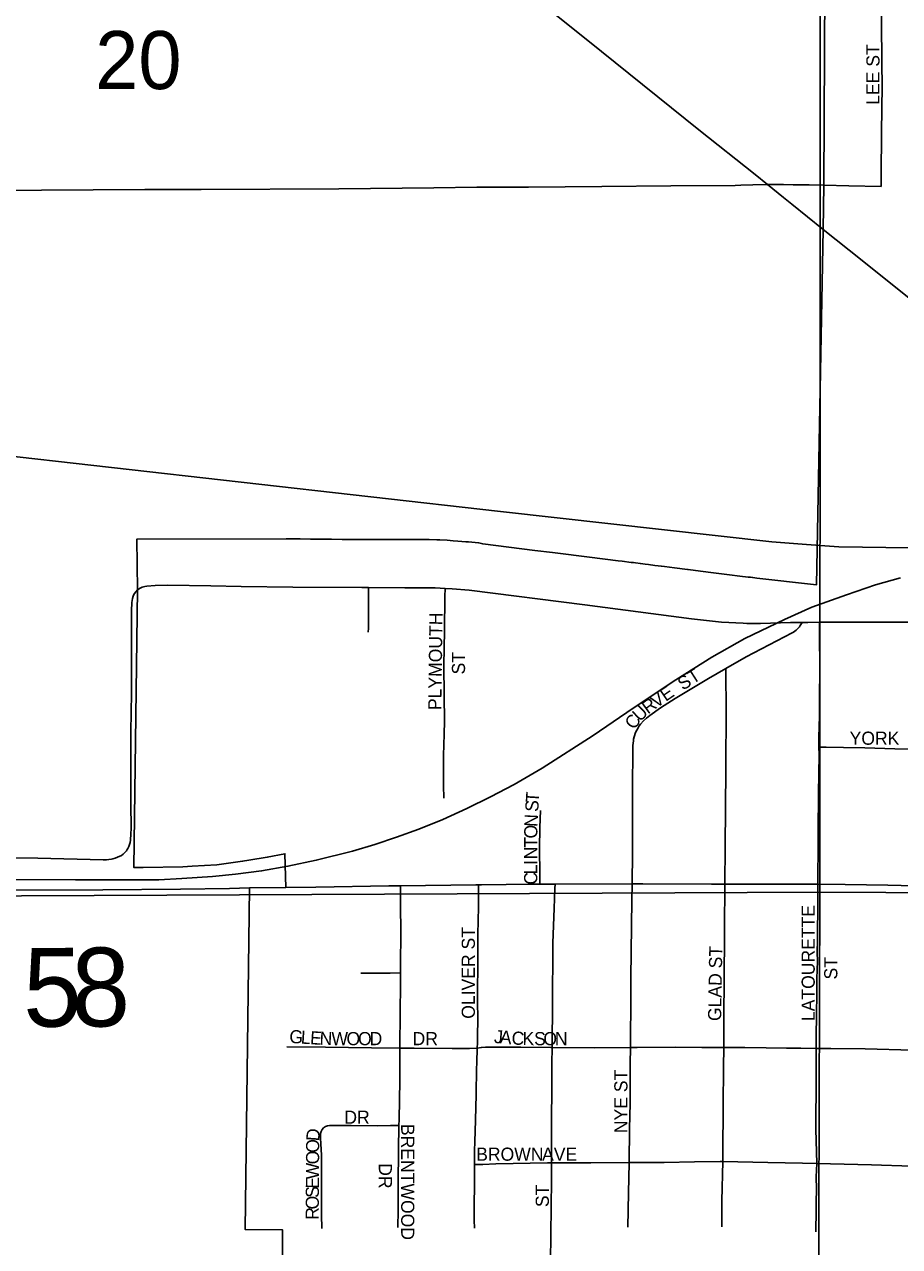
# Model space of a CAD drawing. Extents: x -97 to 34, y -21 to 22.
# Drawn here: x 4.025 to 4.656, y 19.223 to 20.104 of the extents above; entities that cross this region are included whole.
import ezdxf

# ---------------------------------------------------------------- set-up
doc = ezdxf.new("R2010")
doc.units = 0
for name, color, linetype in [('GM_X_City_Street', 7, 'Continuous'), ('GM_X_City_Street_Text', 7, 'Continuous'), ('GM_X_Corporation', 7, 'Continuous'), ('GM_X_County_Road', 7, 'Continuous'), ('GM_X_County_Road_Text', 7, 'Continuous'), ('GM_X_Rail_Line', 7, 'Continuous'), ('GM_X_Section', 7, 'Continuous'), ('GM_X_Section_Text', 7, 'Continuous'), ('GM_X_State_Route', 7, 'Continuous')]:
    doc.layers.add(name, color=color, linetype=linetype)

msp = doc.modelspace()

# ---------------------------------------------------------------- linework, layer by layer
at = {"layer": 'GM_X_City_Street'}
for points in [[(4.64294, 19.98749), (4.64296, 19.99531), (4.64307, 20.02635), (4.64353, 20.06045), (4.64344, 20.07596), (4.64318, 20.1069), (4.64326, 20.11613), (4.64352, 20.13152), (4.64362, 20.16222), (4.64369, 20.17921)], [(4.60166, 19.98837), (4.6197, 19.98805), (4.64294, 19.98749)], [(4.27324, 19.66609), (4.27329, 19.66906), (4.2734, 19.6928), (4.27343, 19.69838)], [(4.32766, 19.54637), (4.3274, 19.55557), (4.32738, 19.57718), (4.32783, 19.59263), (4.32815, 19.60191), (4.32799, 19.62049), (4.3277, 19.64218), (4.32808, 19.66696), (4.32847, 19.69175), (4.32856, 19.69766)], [(4.53101, 19.63991), (4.54552, 19.64826), (4.57865, 19.66563), (4.57969, 19.66618), (4.58067, 19.66686), (4.58171, 19.66757), (4.58319, 19.66891), (4.584, 19.66986), (4.58463, 19.67086), (4.58596, 19.67309)], [(4.59809, 19.58323), (4.59805, 19.59022), (4.59838, 19.60574), (4.59836, 19.61506), (4.59859, 19.643), (4.59858, 19.66162), (4.59856, 19.67326)], [(4.46586, 19.59361), (4.46676, 19.5955), (4.46768, 19.5972), (4.46847, 19.59843), (4.46949, 19.59974), (4.47159, 19.60203), (4.47382, 19.60406), (4.47625, 19.60599), (4.48396, 19.61147), (4.49445, 19.61823), (4.51851, 19.6327), (4.53101, 19.63991)], [(4.53016, 19.4844), (4.53038, 19.51129), (4.53106, 19.56739), (4.53111, 19.61103), (4.53103, 19.63594), (4.53101, 19.63991)], [(4.46333, 19.4846), (4.4636, 19.50688), (4.46361, 19.55348), (4.46384, 19.58144), (4.46396, 19.58438), (4.4643, 19.58762), (4.46448, 19.589), (4.46484, 19.59067), (4.46586, 19.59361)], [(4.59728, 19.48431), (4.59751, 19.51571), (4.59754, 19.53124), (4.59782, 19.54055), (4.59779, 19.54986), (4.59812, 19.57781), (4.59809, 19.58323)], [(4.59809, 19.58323), (4.60332, 19.58314), (4.61567, 19.58295), (4.63108, 19.58269), (4.65267, 19.58195), (4.6676, 19.58171)], [(4.39685, 19.48426), (4.39682, 19.49168), (4.39677, 19.50997), (4.3968, 19.52523), (4.39734, 19.53744)], [(4.21384, 19.482), (4.23545, 19.48214), (4.28815, 19.48317), (4.29643, 19.48326)], [(4.2965, 19.4205), (4.2965, 19.43005), (4.29673, 19.44542), (4.29641, 19.47352), (4.29643, 19.47975), (4.29643, 19.48326)], [(4.29643, 19.48326), (4.35083, 19.48382), (4.3526, 19.48383)], [(4.35178, 19.3661), (4.35187, 19.36999), (4.35205, 19.37587), (4.35222, 19.38567), (4.35197, 19.40126), (4.35201, 19.40437), (4.35197, 19.41358), (4.35215, 19.41935), (4.35224, 19.42584), (4.3521, 19.43205), (4.35214, 19.4373), (4.3522, 19.44484), (4.35223, 19.44952), (4.35242, 19.45668), (4.35261, 19.46919), (4.35262, 19.47572), (4.35263, 19.47882), (4.35263, 19.48259), (4.3526, 19.48383)], [(4.3526, 19.48383), (4.35484, 19.48386), (4.39049, 19.48423), (4.39685, 19.48426)], [(4.39685, 19.48426), (4.40783, 19.48432)], [(4.40572, 19.3666), (4.40576, 19.37053), (4.40608, 19.39538), (4.40631, 19.44203), (4.40712, 19.46692), (4.40771, 19.48132), (4.40783, 19.48432)], [(4.40783, 19.48432), (4.46333, 19.4846)], [(4.46214, 19.36657), (4.46227, 19.37645), (4.46241, 19.39506), (4.4625, 19.41679), (4.4632, 19.4727), (4.46333, 19.4846)], [(4.46333, 19.4846), (4.47113, 19.48464), (4.52072, 19.4844), (4.53016, 19.4844)], [(4.52943, 19.36656), (4.52955, 19.39289), (4.52975, 19.41156), (4.5299, 19.45207), (4.53016, 19.4844)], [(4.53016, 19.4844), (4.58586, 19.48437), (4.59728, 19.48431)], [(4.59598, 19.36586), (4.59597, 19.36985), (4.59633, 19.39467), (4.59643, 19.40087), (4.59647, 19.40397), (4.59661, 19.41327), (4.59658, 19.41637), (4.59694, 19.42878), (4.59679, 19.43499), (4.59697, 19.44431), (4.59719, 19.47225), (4.59728, 19.48431)], [(4.59728, 19.48431), (4.61686, 19.4842), (4.63233, 19.48391), (4.64781, 19.48371), (4.66685, 19.48317)], [(4.26799, 19.42017), (4.28342, 19.42017), (4.28639, 19.42019), (4.28912, 19.42027), (4.2965, 19.4205)], [(4.296, 19.36614), (4.29621, 19.39256), (4.29651, 19.41125), (4.2965, 19.4205)], [(4.21446, 19.36699), (4.2425, 19.36673), (4.27556, 19.36628), (4.296, 19.36614)], [(4.29538, 19.31033), (4.29545, 19.31465), (4.29599, 19.3427), (4.29599, 19.36452), (4.296, 19.36614)], [(4.296, 19.36614), (4.3062, 19.36608), (4.3337, 19.36589), (4.34616, 19.36584), (4.35178, 19.3661)], [(4.34981, 19.28207), (4.34981, 19.28297), (4.3498, 19.29233), (4.35005, 19.29855), (4.35041, 19.31414), (4.35102, 19.33276), (4.35098, 19.339), (4.35115, 19.34521), (4.35124, 19.35099), (4.35142, 19.35569), (4.35178, 19.3661)], [(4.35178, 19.3661), (4.35476, 19.36664), (4.35771, 19.3669), (4.36148, 19.3669), (4.38314, 19.36683), (4.4049, 19.36661), (4.40572, 19.3666)], [(4.40531, 19.28331), (4.4054, 19.31772), (4.40553, 19.33327), (4.4056, 19.35502), (4.40572, 19.3666)], [(4.40572, 19.3666), (4.43596, 19.36629), (4.46214, 19.36657)], [(4.46118, 19.28359), (4.46154, 19.30792), (4.46191, 19.32648), (4.462, 19.35475), (4.46214, 19.36657)], [(4.46214, 19.36657), (4.46703, 19.36662), (4.49499, 19.3667), (4.51361, 19.36654), (4.52943, 19.36656)], [(4.52872, 19.28426), (4.5289, 19.29013), (4.529, 19.32439), (4.52937, 19.35241), (4.52943, 19.36656)], [(4.52943, 19.36656), (4.54459, 19.36658), (4.55999, 19.36628), (4.57465, 19.36601), (4.5849, 19.36599), (4.59598, 19.36586)], [(4.59643, 19.28289), (4.59644, 19.28294), (4.59579, 19.30777), (4.59603, 19.34502), (4.59598, 19.36586)], [(4.59598, 19.36586), (4.60664, 19.36575), (4.63147, 19.36554), (4.66562, 19.36466), (4.6658, 19.36465)], [(4.23966, 19.23605), (4.2396, 19.24585), (4.23955, 19.25491), (4.23944, 19.26759), (4.23944, 19.27847), (4.23944, 19.28892), (4.23887, 19.30119), (4.23883, 19.3046), (4.23922, 19.306), (4.23999, 19.30746), (4.24103, 19.30857), (4.24231, 19.3095), (4.24375, 19.30997), (4.24531, 19.31024), (4.25467, 19.31038), (4.2609, 19.31031), (4.27957, 19.30998), (4.28926, 19.31019), (4.29538, 19.31033)], [(4.2945, 19.23684), (4.29472, 19.24925), (4.29486, 19.26793), (4.29513, 19.29285), (4.29538, 19.31033)], [(4.34989, 19.23631), (4.34955, 19.24204), (4.34955, 19.24629), (4.34964, 19.25811), (4.34982, 19.26213), (4.34981, 19.26665), (4.34985, 19.27051), (4.34981, 19.28207)], [(4.34981, 19.28207), (4.35581, 19.28228), (4.36512, 19.28263), (4.40247, 19.28329), (4.40531, 19.28331)], [(4.40455, 19.20611), (4.4046, 19.21193), (4.40527, 19.27105), (4.40531, 19.28331)], [(4.40531, 19.28331), (4.4336, 19.28346), (4.46118, 19.28359)], [(4.4602, 19.23687), (4.46074, 19.26167), (4.46118, 19.2834), (4.46118, 19.28359)], [(4.46118, 19.28359), (4.48651, 19.28371), (4.50831, 19.28399), (4.52698, 19.28429), (4.52872, 19.28426)], [(4.52806, 19.23712), (4.52813, 19.25589), (4.52872, 19.28426)], [(4.52872, 19.28426), (4.56121, 19.28363), (4.58611, 19.28315), (4.59643, 19.28289)], [(4.59575, 19.2335), (4.59594, 19.23952), (4.59597, 19.24323), (4.59601, 19.24677), (4.59605, 19.25131), (4.59608, 19.25502), (4.59628, 19.26434), (4.5961, 19.27332), (4.59643, 19.28289)], [(4.59643, 19.28289), (4.63586, 19.28191), (4.66497, 19.28102)]]:
    msp.add_lwpolyline(points, dxfattribs=at)
at = {"layer": 'GM_X_Corporation'}
msp.add_lwpolyline([(4.60262, 20.17993), (4.60166, 19.98837), (4.60122, 19.95654), (4.59622, 19.7002), (4.59422, 19.70044), (4.55338, 19.70514), (4.55187, 19.70531), (4.55037, 19.70549), (4.55012, 19.70552), (4.54863, 19.70569), (4.54713, 19.70586), (4.54095, 19.70657), (4.53348, 19.70743), (4.53158, 19.70771), (4.52217, 19.70891), (4.51278, 19.71011), (4.51271, 19.71012), (4.5037, 19.71117), (4.50337, 19.71121), (4.50333, 19.71122), (4.49397, 19.71242), (4.49394, 19.71242), (4.48683, 19.71333), (4.4868, 19.71334), (4.48458, 19.71362), (4.48454, 19.71363), (4.47969, 19.71425), (4.47966, 19.71425), (4.47518, 19.71483), (4.47515, 19.71483), (4.47274, 19.71514), (4.47271, 19.71514), (4.46936, 19.71557), (4.46933, 19.71558), (4.46579, 19.71604), (4.46429, 19.71623), (4.46278, 19.71642), (4.45627, 19.71723), (4.45346, 19.71758), (4.44387, 19.71878), (4.43088, 19.7204), (4.42501, 19.72113), (4.41573, 19.72229), (4.40614, 19.72349), (4.39333, 19.72509), (4.38393, 19.72626), (4.37453, 19.72744), (4.36513, 19.72861), (4.35574, 19.72979), (4.35291, 19.7304), (4.35271, 19.73042), (4.34537, 19.73115), (4.34358, 19.73133), (4.33779, 19.7318), (4.33448, 19.73207), (4.33019, 19.73232), (4.32492, 19.73264), (4.32256, 19.7327), (4.31718, 19.73284), (4.31493, 19.73283), (4.30736, 19.73283), (4.29979, 19.73286), (4.29221, 19.73289), (4.28463, 19.73292), (4.27706, 19.73294), (4.26948, 19.73297), (4.2619, 19.733), (4.25432, 19.73303), (4.24675, 19.73305), (4.23919, 19.7331), (4.23164, 19.73319), (4.23161, 19.73319), (4.22403, 19.73329), (4.21603, 19.73339), (4.21412, 19.73341), (4.10653, 19.7332), (4.10695, 19.69669), (4.1043, 19.49626), (4.11107, 19.49638), (4.13957, 19.49688), (4.14623, 19.49729), (4.16413, 19.4984), (4.17764, 19.50018), (4.18264, 19.50083), (4.18714, 19.50165), (4.20042, 19.50372), (4.21318, 19.50625), (4.21384, 19.482), (4.18765, 19.4816), (4.18445, 19.23534), (4.21143, 19.23497), (4.21247, 18.98027)], dxfattribs=at)
at = {"layer": 'GM_X_County_Road'}
for points in [[(3.61795, 19.98386), (3.65568, 19.98375), (3.75508, 19.98321), (3.83584, 19.98357), (3.87934, 19.98374), (3.91661, 19.98384), (4.03776, 19.98474), (4.11231, 19.98528), (4.1527, 19.98541), (4.2521, 19.98591), (4.32043, 19.98653), (4.35151, 19.98696), (4.38877, 19.98699), (4.44158, 19.98743), (4.49127, 19.9879), (4.5377, 19.98829), (4.54183, 19.98838), (4.55053, 19.9886), (4.5611, 19.9889)], [(4.5611, 19.9889), (4.57243, 19.98882), (4.57958, 19.98878), (4.59095, 19.98861), (4.60166, 19.98837)], [(3.85575, 19.47956), (3.86361, 19.47959), (3.90104, 19.47977), (3.99147, 19.48004), (4.08189, 19.48016), (4.138, 19.48076), (4.17319, 19.4813)], [(4.17319, 19.4813), (4.18765, 19.4816)], [(4.18765, 19.4816), (4.21384, 19.482)]]:
    msp.add_lwpolyline(points, dxfattribs=at)
at = {"layer": 'GM_X_Rail_Line'}
for points in [[(3.55146, 19.84605), (3.99437, 19.79548), (4.36844, 19.75302), (4.56422, 19.73118), (4.58914, 19.72923), (4.61241, 19.7276), (4.66323, 19.72698), (4.72805, 19.72735), (4.75546, 19.72823), (4.77023, 19.72786), (4.81467, 19.72488)], [(3.95355, 19.48799), (4.06219, 19.4874), (4.10693, 19.4874), (4.12239, 19.48759), (4.13882, 19.48837), (4.161, 19.48993), (4.17763, 19.49168), (4.1963, 19.49391), (4.21526, 19.49732), (4.23578, 19.5016), (4.26184, 19.50811), (4.27798, 19.51297), (4.29364, 19.51832), (4.30969, 19.52406), (4.3269, 19.53106), (4.34421, 19.53884), (4.36132, 19.5473), (4.37834, 19.55625), (4.39847, 19.56802), (4.43523, 19.59165), (4.46421, 19.61129), (4.49484, 19.63171), (4.52081, 19.64795), (4.54473, 19.66147), (4.57332, 19.67518), (4.59297, 19.68413), (4.61796, 19.69308), (4.63887, 19.70027), (4.65686, 19.70533)]]:
    msp.add_lwpolyline(points, dxfattribs=at)
at = {"layer": 'GM_X_Section'}
for points in [[(3.62422, 20.47777), (4.59907, 20.48403), (4.59865, 19.47855), (3.60488, 19.47394)], [(4.59907, 20.48403), (5.59805, 20.47457), (5.59615, 19.47364), (4.59865, 19.47855)], [(3.60488, 19.47394), (4.59865, 19.47855), (4.59557, 18.47233), (3.5921, 18.48713)], [(4.59865, 19.47855), (5.59615, 19.47364), (5.59082, 18.47236), (4.59557, 18.47233)]]:
    msp.add_lwpolyline(points, close=True, dxfattribs=at)
at = {"layer": 'GM_X_State_Route'}
for points in [[(3.94192, 20.48218), (4.01136, 20.42739), (4.04519, 20.40046), (4.07681, 20.3753), (4.08165, 20.37141), (4.11813, 20.3424), (4.17415, 20.29802), (4.24221, 20.24385), (4.269, 20.2226), (4.2978, 20.19949), (4.31987, 20.18177), (4.3625, 20.14821), (4.36869, 20.14333), (4.44131, 20.08488), (4.51153, 20.02843), (4.55203, 19.99615), (4.5611, 19.9889), (4.57263, 19.97959), (4.57852, 19.97479), (4.60122, 19.95654)], [(4.60122, 19.95654), (4.62915, 19.93424), (4.66788, 19.90309), (4.72606, 19.85642), (4.74904, 19.83794), (4.78415, 19.80968), (4.80785, 19.79053), (4.82281, 19.77844), (4.84237, 19.76308), (4.85305, 19.75462), (4.8681, 19.74272), (4.87591, 19.73633), (4.88286, 19.73083), (4.89017, 19.72505), (4.89344, 19.72257), (4.89873, 19.71857), (4.91115, 19.70981), (4.93154, 19.69606), (4.94212, 19.68913), (4.94841, 19.68504), (4.95266, 19.68192), (4.95603, 19.67899)], [(4.10695, 19.69669), (4.10873, 19.69773), (4.11038, 19.69847), (4.1122, 19.69899), (4.11353, 19.69924), (4.11959, 19.69976), (4.12883, 19.69996), (4.15988, 19.69945), (4.18162, 19.69901), (4.21889, 19.69844), (4.2686, 19.69842), (4.27343, 19.69838), (4.29965, 19.69817), (4.32136, 19.69797), (4.32856, 19.69766), (4.33372, 19.69743), (4.34605, 19.69627), (4.42922, 19.68572), (4.50622, 19.67579), (4.52786, 19.67339), (4.54341, 19.67251), (4.54599, 19.67245)], [(4.09954, 19.50938), (4.09996, 19.51007), (4.10062, 19.51156), (4.10116, 19.51305), (4.10156, 19.51447), (4.1018, 19.51607), (4.10196, 19.51735), (4.10211, 19.51934), (4.10229, 19.52568), (4.10217, 19.54128), (4.10211, 19.56305), (4.10219, 19.59421), (4.1026, 19.62221), (4.10258, 19.68136), (4.10287, 19.68749), (4.10303, 19.68904), (4.10337, 19.69042), (4.10383, 19.692), (4.10431, 19.69319), (4.10479, 19.69408), (4.10559, 19.6952), (4.10695, 19.69669)], [(4.54599, 19.67245), (4.55588, 19.67222), (4.5776, 19.673), (4.58596, 19.67309), (4.59001, 19.67314), (4.59856, 19.67326), (4.61174, 19.67342), (4.66872, 19.67329), (4.68006, 19.67326), (4.73665, 19.67261)], [(3.80206, 19.50214), (3.82332, 19.50227), (3.83832, 19.50277), (3.85204, 19.50308), (3.88575, 19.50362), (3.97291, 19.50347), (4.03517, 19.50322), (4.08205, 19.50191), (4.08453, 19.50191), (4.08621, 19.50207), (4.08805, 19.50231), (4.08916, 19.50263), (4.09069, 19.50311), (4.09253, 19.50375), (4.0954, 19.50511), (4.0966, 19.50599), (4.0978, 19.50711), (4.09891, 19.50837), (4.09954, 19.50938)]]:
    msp.add_lwpolyline(points, dxfattribs=at)

# ---------------------------------------------------------------- texts
at = {"layer": 'GM_X_City_Street_Text'}
for s, rotation, p in [('LEE ST', 90, (4.64171, 20.04644)), ('PLYMOUTH', 89.2556, (4.32588, 19.60981)), ('ST', 90, (4.343, 19.63561)), ('ST', 32.73207, (4.50003, 19.62378)), ('V', 34.60531, (4.48077, 19.61099)), ('E', 34.56902, (4.48763, 19.61573)), ('U', 44.11907, (4.46905, 19.60103)), ('R', 36.12199, (4.47477, 19.60661)), ('C', 54.85477, (4.46504, 19.59526)), ('YORK', 0.00001, (4.62016, 19.58489)), ('T', 86.41804, (4.39613, 19.54293)), ('S', 86.39127, (4.39571, 19.53627)), ('N', 87.04809, (4.39513, 19.52549)), ('O', 89.47536, (4.39506, 19.51726)), ('T', 90, (4.39506, 19.51062)), ('N', 89.98125, (4.39505, 19.50228)), ('I', 89.95628, (4.39505, 19.49811)), ('L', 89.98213, (4.39505, 19.49144)), ('C', 89.9757, (4.39505, 19.48394)), ('LATOURETTE', 90, (4.59504, 19.38561)), ('OLIVER ST', 90, (4.35005, 19.38728)), ('GLAD ST', 89.0145, (4.52755, 19.38557)), ('ST', 90, (4.61134, 19.41561)), ('G', 356.45639, (4.21611, 19.36989)), ('L', 356.46761, (4.22442, 19.36937)), ('E', 356.44582, (4.23108, 19.36896)), ('N', 357.98865, (4.23801, 19.36854)), ('W', 359.94971, (4.24669, 19.36824)), ('O', 359.99285, (4.25753, 19.36823)), ('O', 359.99285, (4.26587, 19.36823)), ('D', 359.99285, (4.2742, 19.36823)), ('DR', 0.00001, (4.30516, 19.36822)), ('J', 355.31624, (4.36365, 19.36989)), ('A', 355.29625, (4.3678, 19.36955)), ('C', 356.14096, (4.37626, 19.36885)), ('K', 359.36207, (4.38432, 19.36832)), ('S', 359.99563, (4.39277, 19.36823)), ('O', 359.99285, (4.39943, 19.36823)), ('N', 359.99285, (4.40777, 19.36823)), ('NYE ST', 90, (4.46005, 19.30478)), ('DR', 0.00001, (4.256, 19.31156)), ('D', 86.04052, (4.23789, 19.29877)), ('BRENTWOOD', 270, (4.29694, 19.31144)), ('O', 89.64367, (4.23785, 19.29059)), ('BROWN', 0.00001, (4.35099, 19.28489)), ('AVE', 0.00001, (4.3985, 19.28489)), ('O', 89.62837, (4.2378, 19.28226)), ('W', 89.64694, (4.23773, 19.27143)), ('DR', 270, (4.28083, 19.28311)), ('E', 89.63077, (4.23769, 19.26476)), ('ST', 90, (4.40338, 19.25145)), ('O', 89.64367, (4.23759, 19.24976)), ('S', 89.6448, (4.23765, 19.2581)), ('R', 89.63567, (4.23755, 19.24226))]:
    msp.add_text(s, height=0.00947, rotation=rotation, dxfattribs=at).set_placement(p)
at = {"layer": 'GM_X_County_Road_Text'}
for s, rotation, p in [('5', 0.19668, (4.02457, 19.38151)), ('8', 0.29131, (4.0594, 19.38163))]:
    msp.add_text(s, height=0.05682, rotation=rotation, dxfattribs=at).set_placement(p)
at = {"layer": 'GM_X_Section_Text'}
msp.add_text('20', height=0.041856, rotation=0.00001, dxfattribs=at).set_placement((4.07641, 20.05775))

doc.saveas('drawing.dxf')
